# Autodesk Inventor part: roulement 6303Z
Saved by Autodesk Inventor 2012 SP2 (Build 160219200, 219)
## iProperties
Created: 2013-04
Part Number: roulement 6303Z
Material: Default
Document SubType Name: Modeling
Designer: papa
Density: 1 g/cm^3
Mass: 15.0382 g
Surface Area: 109.41 cm^2
Volume: 15.0382 cm^3
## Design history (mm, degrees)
node "roulement 6303Z1"
node "roulement 6303Z"
node "roulement 6303Z_1"
node "roulement 6303Z_2"
node "roulement 6303Z_3"
node "Base1"
node "Base2"
node "Base3"
node "Base4"
